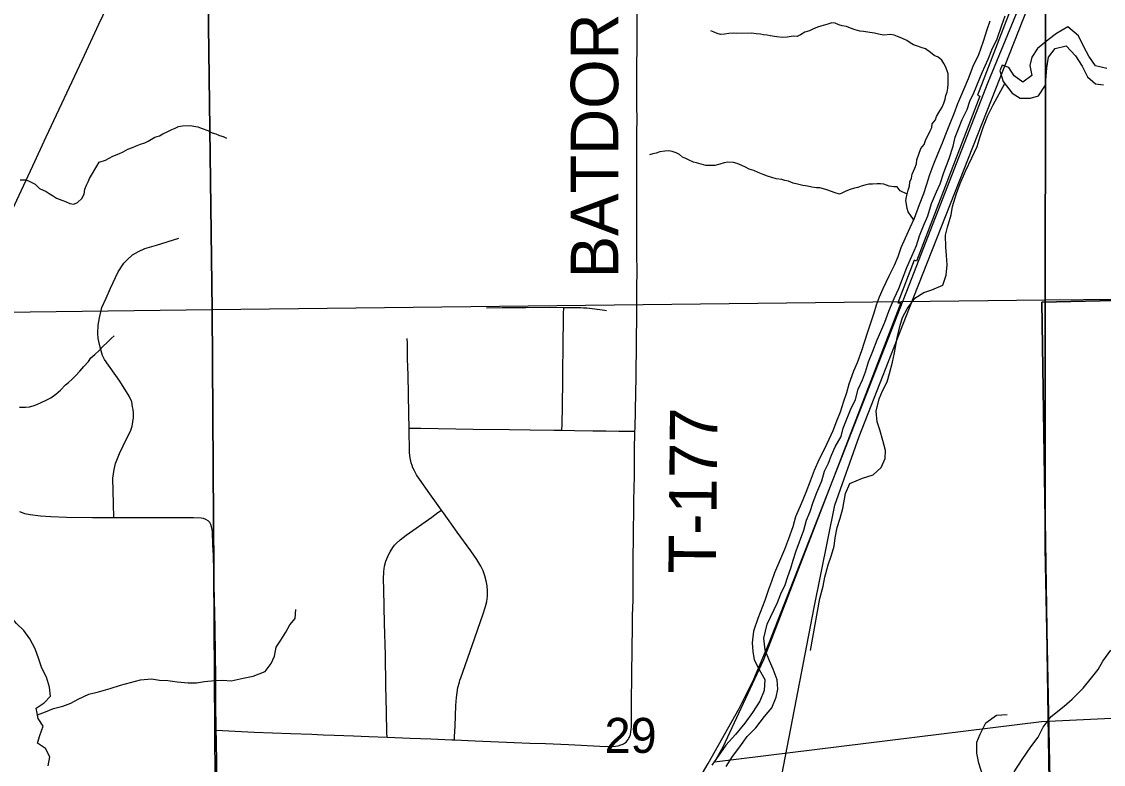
# Model space of a CAD drawing. Extents: x 0 to 34, y 0 to 22.
# Drawn here: x 6.57 to 7.864, y 17.313 to 18.2 of the extents above; entities that cross this region are included whole.
import ezdxf

# ---------------------------------------------------------------- set-up
doc = ezdxf.new("R2010")
doc.units = 0
for name, color, linetype in [('Default', 7, 'Continuous'), ('GM_X_Major_River', 7, 'Continuous'), ('GM_X_Minor_River', 7, 'Continuous'), ('GM_X_Rail_Line', 7, 'Continuous'), ('GM_X_Section', 7, 'Continuous'), ('GM_X_Section_Text', 7, 'Continuous'), ('GM_X_State_Route', 7, 'Continuous'), ('GM_X_Township_Road', 7, 'Continuous'), ('GM_X_Township_Road_Text', 7, 'Continuous')]:
    doc.layers.add(name, color=color, linetype=linetype)

msp = doc.modelspace()

# ---------------------------------------------------------------- linework, layer by layer
at = {"layer": 'Default'}
msp.add_lwpolyline([(7.7739, 18.27), (7.7134, 18.1126), (7.7162, 18.1114), (7.6405, 17.9143), (7.6377, 17.9154), (7.6181, 17.8644), (7.6215, 17.8644), (7.4575, 17.4374), (7.4088, 17.333), (7.3987, 17.3156), (7.7898, 17.3636), (8.3, 17.3879)], dxfattribs=at)
at = {"layer": 'GM_X_Major_River'}
for points in [[(7.474, 17.5059), (7.4781, 17.5162), (7.4833, 17.5272), (7.4866, 17.5371), (7.49, 17.547), (7.4929, 17.5565), (7.4963, 17.5679), (7.5055, 17.5926), (7.5089, 17.6044), (7.5133, 17.615), (7.5167, 17.6261), (7.5211, 17.6375), (7.5271, 17.6516), (7.5304, 17.663), (7.5353, 17.6725), (7.5386, 17.682), (7.5431, 17.6923), (7.5502, 17.7044), (7.5528, 17.7143), (7.5576, 17.7265), (7.5614, 17.7364), (7.5673, 17.7486), (7.5707, 17.7611), (7.5759, 17.7721), (7.5792, 17.782), (7.5829, 17.7938), (7.5882, 17.8064), (7.5934, 17.8201), (7.5978, 17.83), (7.6023, 17.841), (7.6071, 17.8543), (7.6135, 17.8695), (7.6191, 17.8813), (7.6235, 17.8931), (7.6287, 17.9064), (7.6347, 17.9201), (7.6403, 17.9327), (7.644, 17.9445), (7.6488, 17.9562), (7.6541, 17.9684), (7.6585, 17.9829), (7.6641, 17.9969), (7.6686, 18.0065), (7.673, 18.0201), (7.6793, 18.0369), (7.6842, 18.0517), (7.6867, 18.0623), (7.6908, 18.0722), (7.6949, 18.0833), (7.7009, 18.0954), (7.7042, 18.1053), (7.7091, 18.1152), (7.7188, 18.1396), (7.7259, 18.1556), (7.7303, 18.1666), (7.7367, 18.1799), (7.7423, 18.1963), (7.7463, 18.2073)], [(7.7282, 18.2011), (7.7245, 18.1908), (7.72, 18.1767), (7.7145, 18.1608), (7.7077, 18.1467), (7.7022, 18.1322), (7.6966, 18.1189), (7.6895, 18.1022), (7.685, 18.0904), (7.6798, 18.0775), (7.675, 18.0657), (7.6709, 18.0554), (7.6657, 18.0428), (7.6605, 18.0299), (7.656, 18.0174), (7.6519, 18.0044), (7.6486, 17.9945), (7.6437, 17.9816), (7.6374, 17.9653), (7.6322, 17.9538), (7.627, 17.9417), (7.6218, 17.9299), (7.618, 17.9192), (7.6136, 17.909), (7.6072, 17.896), (7.6001, 17.8812), (7.5957, 17.8709), (7.5923, 17.8614), (7.5893, 17.8519), (7.5819, 17.8291), (7.5779, 17.8169), (7.5745, 17.807), (7.5693, 17.7926), (7.5652, 17.7827), (7.5593, 17.7671), (7.5567, 17.7568), (7.553, 17.7462), (7.5489, 17.7336), (7.5448, 17.723), (7.5403, 17.7112), (7.5355, 17.7009), (7.5299, 17.6891), (7.5239, 17.6773), (7.5179, 17.664), (7.5131, 17.6511), (7.5079, 17.6374), (7.5023, 17.6241), (7.4956, 17.6085), (7.4923, 17.5963), (7.4874, 17.5822), (7.4826, 17.5693), (7.4763, 17.5556), (7.4707, 17.5415), (7.467, 17.5313), (7.4632, 17.5214), (7.4589, 17.5083)], [(7.4589, 17.5083), (7.4506, 17.487), (7.4453, 17.4718), (7.4439, 17.4577), (7.4447, 17.4475), (7.4463, 17.4376), (7.452, 17.4259), (7.4589, 17.4138), (7.4582, 17.4009), (7.4529, 17.3879), (7.4443, 17.3746), (7.4349, 17.3617), (7.424, 17.3483), (7.4123, 17.3354), (7.4033, 17.3224), (7.3954, 17.3114)], [(7.4128, 17.3099), (7.4203, 17.3217), (7.429, 17.3336), (7.438, 17.3457), (7.4482, 17.356), (7.4587, 17.3698), (7.4673, 17.38), (7.4726, 17.393), (7.4744, 17.4025), (7.4736, 17.4135), (7.469, 17.4264), (7.4644, 17.4362), (7.4594, 17.4491), (7.4579, 17.4635), (7.4616, 17.4802), (7.474, 17.5059)]]:
    msp.add_lwpolyline(points, dxfattribs=at)
at = {"layer": 'GM_X_Minor_River'}
for points in [[(7.6369, 17.964), (7.6303, 17.9733), (7.6291, 17.9771), (7.6283, 17.9824), (7.6278, 17.9866), (7.6285, 17.9912), (7.6303, 17.9992), (7.6318, 18.0037), (7.6325, 18.0091), (7.6343, 18.0133), (7.635, 18.0182), (7.6383, 18.0255), (7.6402, 18.0304), (7.6409, 18.0354), (7.6456, 18.0487), (7.6494, 18.0537), (7.6516, 18.0595), (7.6546, 18.0656), (7.6568, 18.0698), (7.6586, 18.074), (7.6593, 18.0782), (7.6631, 18.0832), (7.6642, 18.087), (7.6671, 18.0919), (7.6709, 18.0981), (7.6731, 18.103), (7.6745, 18.108), (7.6756, 18.1122), (7.6771, 18.116), (7.6778, 18.121), (7.6781, 18.1263), (7.6784, 18.1312), (7.6783, 18.1381), (7.6771, 18.1418), (7.6752, 18.1468), (7.6732, 18.1505), (7.6705, 18.1543), (7.6663, 18.158), (7.6613, 18.1602), (7.6571, 18.1636), (7.6513, 18.1681), (7.646, 18.1695), (7.6414, 18.171), (7.6368, 18.1728), (7.6326, 18.1751), (7.6288, 18.178), (7.623, 18.1806), (7.6177, 18.1828), (7.6138, 18.1843), (7.6093, 18.185), (7.6009, 18.1845), (7.5948, 18.1856), (7.5902, 18.1866), (7.5845, 18.1877), (7.5769, 18.1887), (7.5727, 18.1891), (7.567, 18.1909), (7.5616, 18.1927), (7.5567, 18.1946), (7.5513, 18.1956), (7.5475, 18.1967), (7.5429, 18.1986), (7.5391, 18.1989), (7.5342, 18.1973), (7.5258, 18.1949), (7.5221, 18.1937), (7.5164, 18.1914), (7.5122, 18.1894), (7.5069, 18.1878), (7.5016, 18.1847), (7.4975, 18.1828), (7.4929, 18.1831), (7.4857, 18.1818), (7.48, 18.1814), (7.4735, 18.1824), (7.4655, 18.1835), (7.4617, 18.1842), (7.4575, 18.1849), (7.4537, 18.1856), (7.4484, 18.1859), (7.4434, 18.1866), (7.4248, 18.1863), (7.421, 18.1867), (7.416, 18.1862), (7.4107, 18.1854), (7.4058, 18.1853), (7.402, 18.1864), (7.3982, 18.1879), (7.3943, 18.1897)], [(7.8463, 18.1591), (7.8409, 18.1697), (7.834, 18.1837), (7.8214, 18.1942), (7.8078, 18.1865), (7.798, 18.1788), (7.7852, 18.1685), (7.7785, 18.1582), (7.7759, 18.148), (7.7783, 18.1362), (7.7677, 18.1282), (7.7571, 18.1357), (7.7509, 18.1455)], [(7.7442, 18.1288), (7.7549, 18.1148), (7.7644, 18.1092), (7.7766, 18.1089), (7.7864, 18.1116), (7.7946, 18.1246), (7.7953, 18.1352), (7.7964, 18.1451), (7.7982, 18.158), (7.8061, 18.1683), (7.8193, 18.1714), (7.8304, 18.1598), (7.8384, 18.1473), (7.8449, 18.1344), (7.8545, 18.1262), (7.8639, 18.1251)], [(7.868, 18.1445), (7.8543, 18.1478), (7.8463, 18.1591)], [(7.7509, 18.1455), (7.7428, 18.1483), (7.7402, 18.1418), (7.7442, 18.1288)], [(7.5135, 17.4486), (7.5247, 17.5108), (7.5287, 17.5257), (7.5309, 17.5363), (7.5346, 17.5511), (7.5387, 17.5625), (7.5417, 17.5732), (7.5431, 17.5834), (7.5453, 17.5956), (7.549, 17.607), (7.5523, 17.6184), (7.5556, 17.6362), (7.5608, 17.6484), (7.5756, 17.6546), (7.5884, 17.6588), (7.5982, 17.6676), (7.6027, 17.6783), (7.6034, 17.6878), (7.5999, 17.6999), (7.5964, 17.7124), (7.5933, 17.7222), (7.5921, 17.7347), (7.5957, 17.7495), (7.5998, 17.7591), (7.6051, 17.7697), (7.608, 17.78), (7.6117, 17.7933), (7.6139, 17.8047), (7.6172, 17.8225), (7.6205, 17.8362), (7.6238, 17.8468), (7.6291, 17.8571), (7.6385, 17.8697), (7.649, 17.8766), (7.6588, 17.8797), (7.6717, 17.8855), (7.6758, 17.8973), (7.6772, 17.9098), (7.6764, 17.9208), (7.6755, 17.931), (7.6751, 17.9451), (7.6776, 17.9549), (7.6817, 17.9694), (7.6835, 17.9793), (7.6883, 17.9952), (7.6924, 18.007), (7.6991, 18.0219), (7.7066, 18.0375), (7.713, 18.0512), (7.7167, 18.0633), (7.7207, 18.0751), (7.7256, 18.0884), (7.7319, 18.101), (7.7459, 18.1266)], [(6.5683, 18.0112), (6.5744, 18.0113), (6.5782, 18.0102), (6.5863, 18.0061), (6.5913, 18.0009), (6.5993, 17.9975), (6.6031, 17.9949), (6.607, 17.9927), (6.6116, 17.9894), (6.6181, 17.9872), (6.6223, 17.9853), (6.6276, 17.9831), (6.6326, 17.9824), (6.6367, 17.9844), (6.642, 17.989), (6.6446, 17.9944), (6.6457, 18.0001), (6.6475, 18.005), (6.6494, 18.0088), (6.6512, 18.0131), (6.6549, 18.0188), (6.6575, 18.0238), (6.6598, 18.0276), (6.6627, 18.0326), (6.6703, 18.035), (6.6745, 18.0373), (6.679, 18.0396), (6.6862, 18.0424), (6.6915, 18.0447), (6.6971, 18.0479), (6.7024, 18.0502), (6.7062, 18.0518), (6.7123, 18.0541), (6.7172, 18.0557), (6.7214, 18.0577), (6.7255, 18.06), (6.7293, 18.0623), (6.735, 18.0639), (6.7387, 18.0663), (6.7448, 18.069), (6.7497, 18.0717), (6.7535, 18.0733), (6.7576, 18.0753), (6.7622, 18.0761), (6.7721, 18.0762), (6.7759, 18.0755), (6.7808, 18.0748), (6.7858, 18.0726), (6.7927, 18.0704), (6.7977, 18.0674)], [(6.7977, 18.0674), (6.8023, 18.0664), (6.8065, 18.0645), (6.811, 18.0631), (6.8149, 18.0612)], [(7.6292, 17.9941), (7.6208, 17.9983), (7.6173, 18.0028), (7.6132, 18.0031), (7.6078, 18.0038), (7.6013, 18.006), (7.5975, 18.0067), (7.5933, 18.0066), (7.5876, 18.0062), (7.5834, 18.0061), (7.5785, 18.0049), (7.574, 18.0037), (7.5702, 18.0021), (7.5664, 18.0013), (7.5611, 17.9997), (7.5558, 17.9978), (7.552, 17.9958), (7.5482, 17.9943), (7.5429, 17.9957), (7.5333, 17.9994), (7.5291, 18.0005), (7.5246, 18.0019), (7.5208, 18.0019), (7.515, 18.0026), (7.5101, 18.0036), (7.5044, 18.0047), (7.4979, 18.0061), (7.4929, 18.0072), (7.4872, 18.0098), (7.483, 18.0105), (7.4792, 18.0116), (7.4727, 18.0126), (7.4673, 18.0141), (7.462, 18.0159), (7.457, 18.0177), (7.4509, 18.0203), (7.4459, 18.0225), (7.4402, 18.0243), (7.436, 18.0266), (7.4314, 18.0284), (7.4257, 18.031), (7.4215, 18.0321), (7.4146, 18.0324), (7.4105, 18.0315), (7.4052, 18.03), (7.3991, 18.0284), (7.3941, 18.0283), (7.3884, 18.0286), (7.3827, 18.03), (7.3774, 18.0315), (7.3735, 18.0326), (7.3686, 18.0348), (7.3644, 18.037), (7.3605, 18.0385), (7.3567, 18.0415), (7.3529, 18.0437), (7.3483, 18.0452), (7.3441, 18.0459), (7.3392, 18.0458), (7.3335, 18.045), (7.3289, 18.0434), (7.3251, 18.0426), (7.321, 18.0414)], [(6.5673, 17.7396), (6.5745, 17.7397), (6.5794, 17.7401), (6.5836, 17.7413), (6.5882, 17.7429), (6.5935, 17.7452), (6.5995, 17.748), (6.6048, 17.7507), (6.6108, 17.755), (6.6165, 17.76), (6.6225, 17.7661), (6.6262, 17.7692), (6.6304, 17.7731), (6.6349, 17.7773), (6.6397, 17.7827), (6.6442, 17.7881), (6.6499, 17.7942), (6.6528, 17.7985), (6.6574, 17.8027), (6.6626, 17.8073), (6.6675, 17.8123), (6.6724, 17.8169), (6.6769, 17.8216), (6.6806, 17.825)], [(6.6034, 17.4048), (6.5997, 17.4166), (6.5941, 17.4276), (6.5907, 17.4382), (6.5862, 17.4508), (6.5798, 17.4626), (6.5727, 17.4725), (6.5637, 17.4809), (6.5525, 17.4941)], [(6.5889, 17.3717), (6.5984, 17.3752), (6.6079, 17.3793), (6.6192, 17.382), (6.6287, 17.3857), (6.6374, 17.3906), (6.6503, 17.3966), (6.662, 17.3992), (6.6757, 17.4033), (6.6882, 17.407), (6.7003, 17.4104), (6.712, 17.4134), (6.7252, 17.4148), (6.7347, 17.4133), (6.7449, 17.4128), (6.7559, 17.4113), (6.7691, 17.4101), (6.7793, 17.41), (6.7888, 17.4115), (6.8009, 17.4129), (6.8107, 17.4133), (6.8205, 17.4125), (6.8349, 17.4154), (6.847, 17.418), (6.8614, 17.4237), (6.8686, 17.4331), (6.8724, 17.4418), (6.8744, 17.4528), (6.8801, 17.4611), (6.8858, 17.4706), (6.8907, 17.4793), (6.8972, 17.4868), (6.898, 17.4978)], [(7.7571, 17.3036), (7.7669, 17.3185), (7.777, 17.3333), (7.7857, 17.3451), (7.7917, 17.3569), (7.8014, 17.3699), (7.8169, 17.3821), (7.8267, 17.3905), (7.8399, 17.4034), (7.8496, 17.416), (7.8575, 17.4259), (7.8632, 17.4358), (7.8729, 17.4491)], [(6.6016, 17.3107), (6.6039, 17.3213), (6.5986, 17.3316), (6.5888, 17.3377), (6.5919, 17.3472), (6.5957, 17.3582), (6.5897, 17.3673), (6.5875, 17.3798), (6.5969, 17.3862), (6.6045, 17.3942), (6.6034, 17.4048)], [(7.7362, 17.2671), (7.7293, 17.2727), (7.725, 17.2852), (7.7197, 17.2989), (7.7151, 17.314), (7.7127, 17.3258), (7.7127, 17.3391), (7.7164, 17.3486), (7.7232, 17.3623), (7.736, 17.3714), (7.7488, 17.3723)]]:
    msp.add_lwpolyline(points, dxfattribs=at)
at = {"layer": 'GM_X_Rail_Line'}
for points in [[(7.4155, 16.9797), (7.4558, 17.1778), (7.5178, 17.4999), (7.5426, 17.6225), (7.5717, 17.7043), (7.6321, 17.8584), (7.8825, 18.4937), (8.0236, 18.8584), (8.1515, 19.1722), (8.1675, 19.2314), (8.3282, 19.8945)], [(7.1956, 16.9797), (7.2748, 17.1151), (7.3911, 17.3137), (7.4282, 17.3794), (7.4457, 17.4145), (7.4643, 17.4578), (7.6315, 17.8854), (7.7259, 18.128), (7.7853, 18.2725), (7.8783, 18.5108), (8.1687, 19.2471)]]:
    msp.add_lwpolyline(points, dxfattribs=at)
at = {"layer": 'GM_X_Section'}
for points in [[(7.7959, 18.8831), (7.7942, 17.8673), (6.7979, 17.8558), (6.7847, 18.8752)], [(8.796, 18.8901), (8.8027, 17.8763), (7.7942, 17.8673), (7.7959, 18.8831)], [(5.6499, 18.8708), (6.7847, 18.8752), (6.7979, 17.8558), (5.6465, 17.841), (5.6468, 17.9172)], [(7.9972, 16.8792), (8.802, 16.8756), (8.8106, 17.3801), (8.8027, 17.8763), (7.7942, 17.8673), (7.7942, 17.5709), (7.8062, 16.9797), (7.9972, 16.9797)], [(7.8062, 16.9797), (7.7942, 17.5709), (7.7942, 17.8673), (6.7979, 17.8558), (6.8036, 16.9797)], [(6.8036, 16.9797), (6.7979, 17.8558), (5.6465, 17.841), (5.6459, 16.8927), (5.644, 16.8278), (5.7774, 16.8294), (5.7774, 16.9797)]]:
    msp.add_lwpolyline(points, close=True, dxfattribs=at)
at = {"layer": 'GM_X_State_Route'}
for points in [[(5.7774, 16.9797), (7.8038, 16.9797), (7.7904, 17.865), (8.296, 17.8766), (8.8033, 17.8763), (8.7984, 18.8872), (8.9, 18.8876), (8.9, 20.9), (5.6507, 20.9)], [(6.3821, 17.599), (6.4307, 17.7019), (6.4457, 17.7335), (6.4637, 17.773), (6.4823, 17.8124), (6.5035, 17.8574), (6.5052, 17.8611), (6.519, 17.8912), (6.5338, 17.922), (6.5641, 17.9871), (6.5832, 18.0282), (6.5992, 18.0626), (6.6428, 18.1554), (6.6624, 18.1976), (6.6772, 18.2284), (6.6942, 18.265), (6.7048, 18.2872), (6.7086, 18.2954), (6.711, 18.3009), (6.7153, 18.3097), (6.7178, 18.3149)]]:
    msp.add_lwpolyline(points, dxfattribs=at)
msp.add_lwpolyline([(7.8042, 16.2626), (7.8024, 15.8725), (6.7968, 15.8774), (5.6416, 15.8841), (5.6436, 15.468), (5.6455, 14.1), (8.9, 14.1), (8.9, 18.8876), (8.7984, 18.8872), (8.8033, 17.8763), (8.296, 17.8766), (7.7904, 17.865), (7.8038, 16.9797), (7.9972, 16.9797), (7.9972, 16.2626)], close=True, dxfattribs=at)
at = {"layer": 'GM_X_Township_Road'}
for points in [[(7.3036, 17.7109), (7.3037, 17.7142), (7.3043, 17.7359), (7.305, 17.7762), (7.3054, 17.8165), (7.3056, 17.8259), (7.3057, 17.8414), (7.3057, 17.8569), (7.3058, 17.8631), (7.3059, 17.866), (7.306, 17.8716), (7.306, 17.8813), (7.306, 17.8887), (7.3061, 17.896), (7.3061, 17.9012), (7.3061, 17.9053), (7.3061, 17.9107), (7.306, 17.9137), (7.306, 17.9261), (7.3059, 17.9354), (7.3059, 17.9509), (7.3058, 17.9634), (7.3057, 17.9726), (7.3059, 17.9851), (7.3058, 18.0006), (7.3057, 18.0031), (7.3058, 18.0062), (7.306, 18.0342), (7.306, 18.0684), (7.3061, 18.0839), (7.306, 18.0995), (7.3059, 18.1399), (7.3061, 18.1771), (7.3062, 18.1896), (7.3062, 18.1923), (7.3062, 18.1977), (7.3063, 18.2224)], [(6.6804, 17.6072), (6.6797, 17.6241), (6.6791, 17.6546), (6.6797, 17.6599), (6.6806, 17.6652), (6.6824, 17.6721), (6.6872, 17.6842), (6.6959, 17.7025), (6.7001, 17.7109), (6.702, 17.7169), (6.7029, 17.722), (6.7036, 17.7271), (6.7036, 17.7324), (6.7034, 17.7368), (6.7027, 17.7399), (6.7016, 17.7458), (6.6985, 17.7529), (6.6875, 17.7708), (6.6689, 17.7964), (6.6669, 17.8015), (6.6638, 17.8114), (6.6616, 17.8216), (6.661, 17.8282), (6.6616, 17.8377), (6.6632, 17.8465), (6.666, 17.8587), (6.6711, 17.8699), (6.6764, 17.8819), (6.6855, 17.9013), (6.6921, 17.9117), (6.6963, 17.9159), (6.7025, 17.9218), (6.7096, 17.9256), (6.7175, 17.9291), (6.7312, 17.9333), (6.7581, 17.9417)], [(7.1261, 17.8585), (7.1448, 17.8589), (7.1729, 17.8589), (7.201, 17.8592), (7.2184, 17.8589)], [(7.2163, 17.7119), (7.2164, 17.719), (7.2168, 17.7409), (7.2173, 17.7722), (7.2178, 17.8223), (7.2181, 17.8374), (7.2183, 17.8451), (7.2183, 17.8508), (7.2184, 17.8589)], [(7.2184, 17.8589), (7.2302, 17.8589), (7.2353, 17.8588), (7.239, 17.8587), (7.2419, 17.8585), (7.246, 17.8582), (7.2526, 17.8575), (7.2674, 17.8557), (7.2696, 17.8553)], [(7.0335, 17.7146), (7.0332, 17.7317), (7.0323, 17.7782), (7.0317, 17.7969), (7.0314, 17.8155), (7.031, 17.8217)], [(7.0335, 17.7146), (7.0383, 17.7146), (7.0476, 17.7145), (7.1099, 17.7133), (7.1535, 17.7127), (7.1784, 17.7125), (7.2065, 17.7119), (7.2163, 17.7119)], [(7.0721, 17.6166), (7.0583, 17.6358), (7.0457, 17.6535), (7.0424, 17.6587), (7.0394, 17.6642), (7.0381, 17.667), (7.037, 17.6699), (7.0361, 17.6729), (7.0348, 17.6789), (7.0341, 17.6851), (7.0335, 17.7146)], [(7.2163, 17.7119), (7.2314, 17.7117), (7.2533, 17.7114), (7.2689, 17.7111), (7.2844, 17.7109), (7.2937, 17.7108), (7.3002, 17.7109), (7.3036, 17.7109)], [(7.293, 17.3391), (7.2944, 17.3408), (7.2955, 17.3423), (7.2963, 17.3439), (7.297, 17.3451), (7.2981, 17.3481), (7.2988, 17.3512), (7.2992, 17.3543), (7.2994, 17.3575), (7.2994, 17.3638), (7.2994, 17.3753), (7.2994, 17.3811), (7.2994, 17.3886), (7.2996, 17.3985), (7.2997, 17.4075), (7.2998, 17.4194), (7.2998, 17.4274), (7.3001, 17.4432), (7.3004, 17.4594), (7.3005, 17.4687), (7.3007, 17.478), (7.3008, 17.4904), (7.3009, 17.4997), (7.3013, 17.5087), (7.3013, 17.5133), (7.3014, 17.5173), (7.3014, 17.5293), (7.3014, 17.5604), (7.3015, 17.5634), (7.3017, 17.5789), (7.3019, 17.5906), (7.302, 17.5975), (7.3022, 17.6098), (7.3023, 17.6166), (7.3024, 17.624), (7.3024, 17.6309), (7.3027, 17.6397), (7.3028, 17.646), (7.3031, 17.6539), (7.3031, 17.6817), (7.3031, 17.6892), (7.3032, 17.6932), (7.3035, 17.7049), (7.3036, 17.7109)], [(6.8028, 17.3532), (6.8024, 17.3857), (6.8022, 17.4168), (6.802, 17.4448), (6.8014, 17.4757), (6.8006, 17.5098), (6.8, 17.544), (6.7994, 17.5626), (6.7988, 17.5749), (6.7981, 17.5904), (6.7978, 17.5934), (6.7972, 17.5964), (6.7964, 17.5991), (6.7949, 17.6016), (6.793, 17.6037), (6.7905, 17.6054), (6.7876, 17.6063), (6.7847, 17.6069), (6.7756, 17.6074), (6.7601, 17.6074), (6.7291, 17.6072), (6.6919, 17.6071), (6.6804, 17.6072), (6.6547, 17.6072), (6.6236, 17.6077), (6.605, 17.6084), (6.5925, 17.6094), (6.5801, 17.6109), (6.5739, 17.6122), (6.5709, 17.6132), (6.568, 17.6144)], [(7.0072, 17.345), (7.007, 17.3503), (7.0063, 17.3751), (7.0057, 17.4062), (7.0051, 17.4436), (7.0042, 17.4809), (7.0032, 17.5214), (7.003, 17.5338), (7.0033, 17.5432), (7.0036, 17.5463), (7.0042, 17.5493), (7.0058, 17.5553), (7.0079, 17.5612), (7.0092, 17.564), (7.0107, 17.5667), (7.0141, 17.5719), (7.016, 17.5744), (7.0181, 17.5767), (7.0226, 17.5809), (7.03, 17.5867), (7.0605, 17.6081), (7.068, 17.6136), (7.0721, 17.6166)], [(7.0877, 17.3417), (7.0879, 17.346), (7.0885, 17.3583), (7.0894, 17.383), (7.0901, 17.3923), (7.0908, 17.3985), (7.0919, 17.4045), (7.0936, 17.4107), (7.0943, 17.4131), (7.0952, 17.4161), (7.1087, 17.4545), (7.1222, 17.4925), (7.125, 17.5014), (7.1263, 17.5074), (7.1271, 17.5136), (7.1272, 17.5198), (7.1268, 17.526), (7.1258, 17.5321), (7.1242, 17.5381), (7.122, 17.544), (7.1193, 17.5495), (7.1145, 17.5575), (7.1074, 17.5677), (7.0908, 17.5902), (7.0747, 17.6131), (7.0721, 17.6166)], [(6.8055, 16.9797), (6.8053, 16.9961), (6.8052, 17.0396), (6.8051, 17.0769), (6.8048, 17.1173), (6.8042, 17.1794), (6.8043, 17.226), (6.8037, 17.2602), (6.8033, 17.313), (6.8029, 17.3409), (6.8028, 17.3532)], [(6.8028, 17.3532), (6.8482, 17.3511), (6.8918, 17.3494), (6.917, 17.3484), (6.9306, 17.3479), (6.9438, 17.3474), (6.9671, 17.3465), (6.9854, 17.3458), (7.0072, 17.345)], [(7.0072, 17.345), (7.0347, 17.344), (7.0595, 17.3429), (7.0844, 17.3419), (7.0877, 17.3417)], [(7.0877, 17.3417), (7.1124, 17.3406), (7.159, 17.3386), (7.1777, 17.338), (7.1964, 17.3373), (7.2243, 17.3362), (7.2616, 17.3344), (7.2741, 17.334), (7.2804, 17.3343), (7.2836, 17.3348), (7.2867, 17.3357), (7.2881, 17.3362), (7.2897, 17.337), (7.2911, 17.3378), (7.293, 17.3391)]]:
    msp.add_lwpolyline(points, dxfattribs=at)

# ---------------------------------------------------------------- texts
at = {"layer": 'GM_X_Section_Text'}
msp.add_text('29', height=0.04186, rotation=0, dxfattribs=at).set_placement((7.2672, 17.3262))
at = {"layer": 'GM_X_Township_Road_Text'}
for s, rotation, p in [('BATDORF', 90, (7.2836, 17.8936)), ('T-177', 89.4378, (7.4004, 17.5403))]:
    msp.add_text(s, height=0.05682, rotation=rotation, dxfattribs=at).set_placement(p)

doc.saveas('drawing.dxf')
